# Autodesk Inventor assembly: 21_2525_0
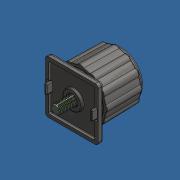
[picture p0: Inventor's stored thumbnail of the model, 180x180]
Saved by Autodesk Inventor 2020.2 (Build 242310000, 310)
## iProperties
Created: 2021-04
Part Number: 21_2525_0
Document SubType Name: Assembly
Designer: amoles
Mass: 117 g
Surface Area: 314.799 cm^2
Volume: 47.5152 cm^3
Sending System: MiniTec Maschinenbau GmbH & Co.KG
Major Version: 4.0
Minor Version: 0.0
Format Version: 0.0
Product Id: MiniTec Maschinenbau GmbH & Co.KG
Art.-Nr.: 21.2525/0
L: -
Stück: 1
5: Stellfuß 45 compact
7: 21.2525/0
8: MiniTec Maschinenbau GmbH & Co KG
Bestellnummer: 21.2525/0
Beschreibung: Stellfuß 45 compact
Länge: -
Artikelnr: 21.2525/0
Lieferant: MiniTec Maschinenbau GmbH & Co KG
Author: amoles
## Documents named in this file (6)
- Y:\INVENTOR LIBRARIES\PARTS LIBRARY\FEET WHEELS FLOOR FASTENING SUPPORTS\21.2525 FOOT 45 COMPACT.iam
- Y:\INVENTOR LIBRARIES\PARTS LIBRARY\FEET WHEELS FLOOR FASTENING SUPPORTS\SUBCOMPONENTS\21.2525 M8 NUT.ipt
- Y:\INVENTOR LIBRARIES\PARTS LIBRARY\FEET WHEELS FLOOR FASTENING SUPPORTS\SUBCOMPONENTS\21.2525 RUBBER PAD.ipt
- Y:\INVENTOR LIBRARIES\PARTS LIBRARY\FEET WHEELS FLOOR FASTENING SUPPORTS\SUBCOMPONENTS\21.2525 LEVELING COMPONENT.ipt
- Y:\INVENTOR LIBRARIES\PARTS LIBRARY\FEET WHEELS FLOOR FASTENING SUPPORTS\SUBCOMPONENTS\21.2525 UPPER HOUSING.ipt
- Y:\INVENTOR LIBRARIES\PARTS LIBRARY\FEET WHEELS FLOOR FASTENING SUPPORTS\SUBCOMPONENTS\21.2525 THREADED STUD.ipt
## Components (5 placed, 5 different names)
1. 21_2525_0_1:1 — Mate:3
2. 21_2525_0_2:1 — Insert:2, Mate:4
3. 21_2525_0_3:1 — Mate:2, Insert:2, Mate:3
4. 21_2525_0_4:1 — Flush:1, Mate:1, Angle:1, Insert:3, Mate:4
5. 21_2525_0_5:1 — Mate:2, Insert:3
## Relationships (8: Mate 4, Insert 2, Flush 1, Angle 1)
- Flush:1: 21_2525_0_4:1
- Mate:1: 21_2525_0_4:1
- Angle:1: 21_2525_0_4:1
- Mate:2: 21_2525_0_3:1 ↔ 21_2525_0_5:1
- Insert:2: 21_2525_0_2:1 ↔ 21_2525_0_3:1
- Mate:3: 21_2525_0_1:1 ↔ 21_2525_0_3:1
- Insert:3: 21_2525_0_4:1 ↔ 21_2525_0_5:1
- Mate:4: 21_2525_0_2:1 ↔ 21_2525_0_4:1
